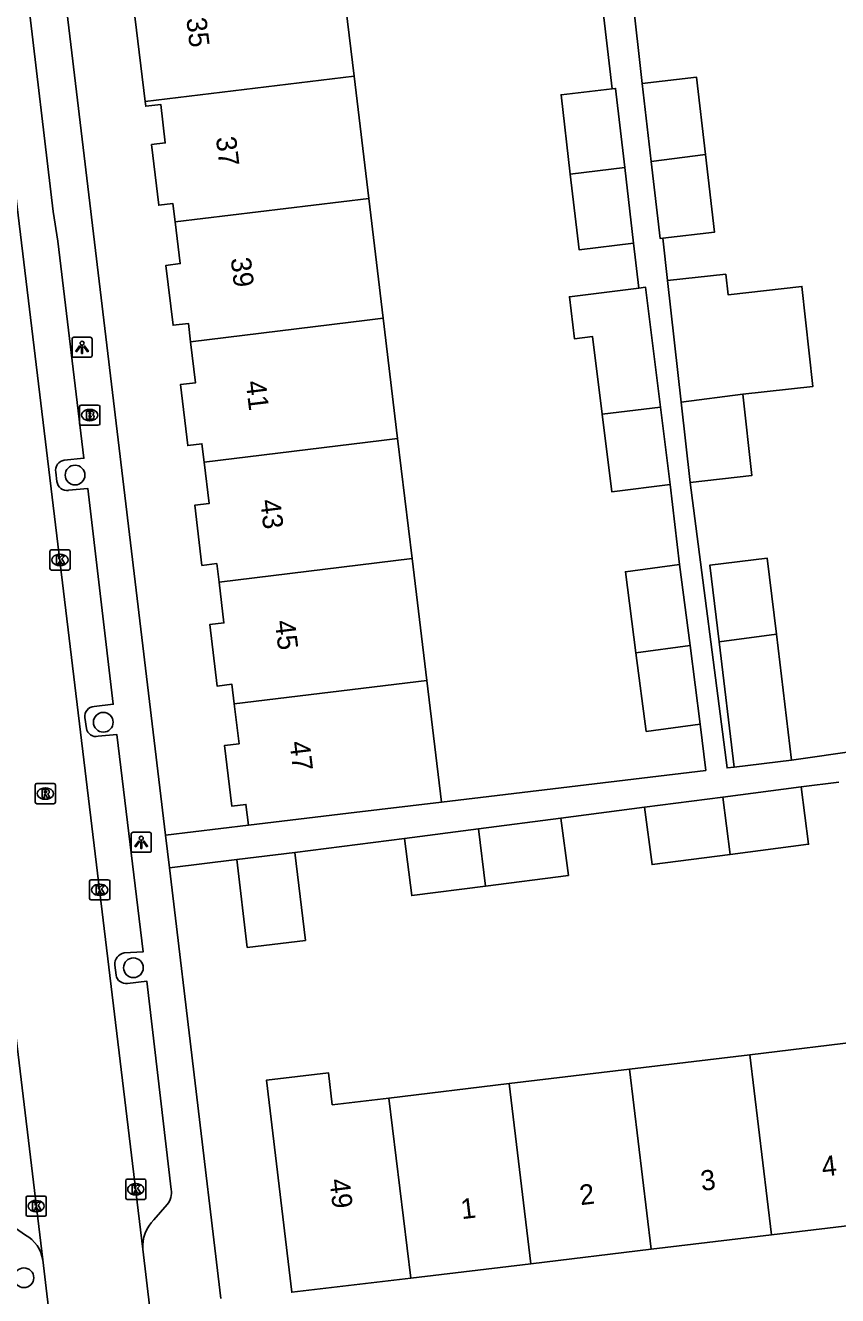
# Model space of a CAD drawing. Extents: x 162074 to 163034, y 381824 to 382557.
# Drawn here: x 162361.6 to 162401.9, y 382279.2 to 382342.2 of the extents above; entities that cross this region are included whole.
import ezdxf

# ---------------------------------------------------------------- set-up
doc = ezdxf.new("R2010")
doc.units = 0
for name, color, linetype in [('IMGEO_Boom', 7, 'Continuous'), ('IMGEO_Brandkraan', 7, 'Continuous'), ('IMGEO_Kolk', 7, 'Continuous'), ('IMGEO_Lichtpunt', 7, 'Continuous'), ('IMGEO_Pand', 7, 'Continuous'), ('IMGEO_Pand_nummerreeks', 7, 'Continuous'), ('IMGEO_Rijbaan_lokaal_open', 7, 'Continuous'), ('IMGEO_Rioolput', 7, 'Continuous'), ('IMGEO_Voetpad_open', 7, 'Continuous')]:
    doc.layers.add(name, color=color, linetype=linetype)

msp = doc.modelspace()

# ---------------------------------------------------------------- linework, layer by layer
at = {"layer": 'IMGEO_Boom'}
for centre in [(162364.081, 382319.909), (162365.485, 382307.641), (162366.981, 382295.456), (162361.545, 382280.073)]:
    msp.add_circle(centre, 0.489, dxfattribs=at)
at = {"layer": 'IMGEO_Brandkraan'}
for p, q in [((162364.309, 382322.46), (162364.309, 382323.312)), ((162364.384, 382323.386), (162365.236, 382323.386)), ((162364.797, 382323.166), (162364.822, 382323.166)), ((162365.31, 382323.312), (162365.31, 382322.46)), ((162365.236, 382322.386), (162364.384, 382322.386)), ((162364.82, 382322.606), (162364.795, 382322.606))]:
    msp.add_line(p, q, dxfattribs=at)
for points in [[(162364.309, 382322.46), (162364.309, 382323.312)], [(162364.384, 382323.386), (162365.236, 382323.386)], [(162364.657, 382323.086), (162364.657, 382322.686), (162364.87, 382322.686)], [(162364.888, 382323.086), (162364.657, 382323.086)], [(162364.836, 382323.005), (162364.782, 382323.005), (162364.782, 382322.929)], [(162364.782, 382322.929), (162364.835, 382322.929)], [(162364.844, 382322.853), (162364.782, 382322.853), (162364.782, 382322.772)], [(162365.31, 382323.312), (162365.31, 382322.46)], [(162365.236, 382322.386), (162364.384, 382322.386)], [(162364.782, 382322.772), (162364.844, 382322.772)]]:
    msp.add_lwpolyline(points, dxfattribs=at)
for centre, radius, start, end in [((162364.386, 382323.31), 0.0765, 91.55205, 178.44795), ((162364.386, 382323.31), 0.0765, 91.55205, 178.44795), ((162364.837, 382322.967), 0.0379, 267.82845, 90.93552), ((162364.845, 382322.812), 0.0404, 269.87594, 90.50774), ((162364.892, 382322.941), 0.145, 59.4692, 91.53667), ((162364.917, 382322.988), 0.0922, 285.51372, 58.15012), ((162364.922, 382322.796), 0.105, 301.31148, 78.98903), ((162365.234, 382323.31), 0.0765, 1.55205, 88.44795), ((162365.234, 382323.31), 0.0765, 1.55205, 88.44795), ((162364.386, 382322.462), 0.0765, 181.55205, 268.44795), ((162364.386, 382322.462), 0.0765, 181.55205, 268.44795), ((162364.876, 382322.937), 0.251, 268.66757, 293.53466), ((162365.234, 382322.462), 0.0765, 271.55205, 358.44795), ((162365.234, 382322.462), 0.0765, 271.55205, 358.44795)]:
    msp.add_arc(centre, radius, start, end, dxfattribs=at)
for centre, major_axis, ratio, start_param, end_param in [((162364.796, 382322.886), (-0.387, 0.002), 0.722429, 4.712389, 7.853982), ((162364.821, 382322.886), (-0.39, 0.002), 0.717154, 1.570796, 4.712389)]:
    msp.add_ellipse(centre, major_axis=major_axis, ratio=ratio, start_param=start_param, end_param=end_param, dxfattribs=at)
at = {"layer": 'IMGEO_Kolk'}
for p, q in [((162362.833, 382315.271), (162362.833, 382316.123)), ((162362.908, 382316.197), (162363.76, 382316.197)), ((162363.321, 382315.977), (162363.346, 382315.977)), ((162363.834, 382316.123), (162363.834, 382315.271)), ((162363.344, 382315.417), (162363.319, 382315.417)), ((162363.76, 382315.197), (162362.908, 382315.197)), ((162364.805, 382298.9), (162364.805, 382299.752)), ((162364.88, 382299.826), (162365.732, 382299.826)), ((162365.293, 382299.606), (162365.318, 382299.606)), ((162365.806, 382299.752), (162365.806, 382298.9)), ((162365.316, 382299.046), (162365.291, 382299.046)), ((162365.732, 382298.826), (162364.88, 382298.826)), ((162366.596, 382284.04), (162366.596, 382284.892)), ((162366.671, 382284.966), (162367.523, 382284.966)), ((162367.084, 382284.746), (162367.109, 382284.746)), ((162367.597, 382284.892), (162367.597, 382284.04)), ((162361.651, 382283.204), (162361.651, 382284.056)), ((162361.726, 382284.13), (162362.578, 382284.13)), ((162362.139, 382283.91), (162362.164, 382283.91)), ((162362.652, 382284.056), (162362.652, 382283.204)), ((162367.523, 382283.966), (162366.671, 382283.966)), ((162367.107, 382284.186), (162367.082, 382284.186)), ((162362.578, 382283.13), (162361.726, 382283.13)), ((162362.162, 382283.35), (162362.137, 382283.35))]:
    msp.add_line(p, q, dxfattribs=at)
for points in [[(162362.833, 382315.271), (162362.833, 382316.123)], [(162362.908, 382316.197), (162363.76, 382316.197)], [(162363.154, 382315.897), (162363.277, 382315.897), (162363.277, 382315.746), (162363.407, 382315.897), (162363.571, 382315.897), (162363.425, 382315.746), (162363.578, 382315.497), (162363.426, 382315.497), (162363.341, 382315.661), (162363.277, 382315.594), (162363.277, 382315.497), (162363.154, 382315.497), (162363.154, 382315.897)], [(162363.834, 382316.123), (162363.834, 382315.271)], [(162363.76, 382315.197), (162362.908, 382315.197)], [(162364.805, 382298.9), (162364.805, 382299.752)], [(162364.88, 382299.826), (162365.732, 382299.826)], [(162365.126, 382299.526), (162365.249, 382299.526), (162365.249, 382299.375), (162365.379, 382299.526), (162365.543, 382299.526), (162365.397, 382299.375), (162365.55, 382299.126), (162365.398, 382299.126), (162365.313, 382299.29), (162365.249, 382299.223), (162365.249, 382299.126), (162365.126, 382299.126), (162365.126, 382299.526)], [(162365.806, 382299.752), (162365.806, 382298.9)], [(162365.732, 382298.826), (162364.88, 382298.826)], [(162366.596, 382284.04), (162366.596, 382284.892)], [(162366.671, 382284.966), (162367.523, 382284.966)], [(162366.917, 382284.666), (162367.04, 382284.666), (162367.04, 382284.515), (162367.17, 382284.666), (162367.334, 382284.666), (162367.188, 382284.515), (162367.341, 382284.266), (162367.189, 382284.266), (162367.104, 382284.43), (162367.04, 382284.363), (162367.04, 382284.266), (162366.917, 382284.266), (162366.917, 382284.666)], [(162367.597, 382284.892), (162367.597, 382284.04)], [(162361.651, 382283.204), (162361.651, 382284.056)], [(162361.726, 382284.13), (162362.578, 382284.13)], [(162361.972, 382283.83), (162362.095, 382283.83), (162362.095, 382283.679), (162362.225, 382283.83), (162362.389, 382283.83), (162362.243, 382283.679), (162362.396, 382283.43), (162362.244, 382283.43), (162362.159, 382283.594), (162362.095, 382283.527), (162362.095, 382283.43), (162361.972, 382283.43), (162361.972, 382283.83)], [(162362.652, 382284.056), (162362.652, 382283.204)], [(162367.523, 382283.966), (162366.671, 382283.966)], [(162362.578, 382283.13), (162361.726, 382283.13)]]:
    msp.add_lwpolyline(points, dxfattribs=at)
for centre, start, end in [((162362.91, 382316.121), 91.55205, 178.44795), ((162362.91, 382316.121), 91.55205, 178.44795), ((162363.758, 382316.121), 1.55205, 88.44795), ((162363.758, 382316.121), 1.55205, 88.44795), ((162362.91, 382315.273), 181.55205, 268.44795), ((162362.91, 382315.273), 181.55205, 268.44795), ((162363.758, 382315.273), 271.55205, 358.44795), ((162363.758, 382315.273), 271.55205, 358.44795), ((162364.882, 382299.75), 91.55205, 178.44795), ((162364.882, 382299.75), 91.55205, 178.44795), ((162365.73, 382299.75), 1.55205, 88.44795), ((162365.73, 382299.75), 1.55205, 88.44795), ((162364.882, 382298.902), 181.55205, 268.44795), ((162364.882, 382298.902), 181.55205, 268.44795), ((162365.73, 382298.902), 271.55205, 358.44795), ((162365.73, 382298.902), 271.55205, 358.44795), ((162366.673, 382284.89), 91.55205, 178.44795), ((162366.673, 382284.89), 91.55205, 178.44795), ((162367.521, 382284.89), 1.55205, 88.44795), ((162367.521, 382284.89), 1.55205, 88.44795), ((162361.728, 382284.054), 91.55205, 178.44795), ((162361.728, 382284.054), 91.55205, 178.44795), ((162362.576, 382284.054), 1.55205, 88.44795), ((162362.576, 382284.054), 1.55205, 88.44795), ((162366.673, 382284.042), 181.55205, 268.44795), ((162366.673, 382284.042), 181.55205, 268.44795), ((162367.521, 382284.042), 271.55205, 358.44795), ((162367.521, 382284.042), 271.55205, 358.44795), ((162361.728, 382283.206), 181.55205, 268.44795), ((162361.728, 382283.206), 181.55205, 268.44795), ((162362.576, 382283.206), 271.55205, 358.44795), ((162362.576, 382283.206), 271.55205, 358.44795)]:
    msp.add_arc(centre, 0.0765, start, end, dxfattribs=at)
for centre, major_axis, ratio, start_param, end_param in [((162363.32, 382315.697), (-0.387, 0.002), 0.722429, 4.712389, 7.853982), ((162363.345, 382315.697), (-0.39, 0.002), 0.717154, 1.570796, 4.712389), ((162365.292, 382299.326), (-0.387, 0.002), 0.722429, 4.712389, 7.853982), ((162365.317, 382299.326), (-0.39, 0.002), 0.717154, 1.570796, 4.712389), ((162367.083, 382284.466), (-0.387, 0.002), 0.722429, 4.712389, 7.853982), ((162367.108, 382284.466), (-0.39, 0.002), 0.717154, 1.570796, 4.712389), ((162362.138, 382283.63), (-0.387, 0.002), 0.722429, 4.712389, 7.853982), ((162362.163, 382283.63), (-0.39, 0.002), 0.717154, 1.570796, 4.712389)]:
    msp.add_ellipse(centre, major_axis=major_axis, ratio=ratio, start_param=start_param, end_param=end_param, dxfattribs=at)
at = {"layer": 'IMGEO_Lichtpunt'}
for p, q in [((162363.933, 382326.656), (162363.933, 382325.849)), ((162363.933, 382326.656), (162363.933, 382325.849)), ((162364.835, 382326.751), (162364.027, 382326.751)), ((162364.835, 382326.751), (162364.027, 382326.751)), ((162364.929, 382325.849), (162364.929, 382326.656)), ((162364.929, 382325.849), (162364.929, 382326.656)), ((162364.027, 382325.755), (162364.835, 382325.755)), ((162364.027, 382325.755), (162364.835, 382325.755)), ((162366.869, 382302.089), (162366.869, 382301.282)), ((162366.869, 382302.089), (162366.869, 382301.282)), ((162367.771, 382302.184), (162366.963, 382302.184)), ((162367.771, 382302.184), (162366.963, 382302.184)), ((162367.865, 382301.282), (162367.865, 382302.089)), ((162367.865, 382301.282), (162367.865, 382302.089)), ((162366.963, 382301.188), (162367.771, 382301.188)), ((162366.963, 382301.188), (162367.771, 382301.188))]:
    msp.add_line(p, q, dxfattribs=at)
for points in [[(162364.307, 382326.32), (162364.346, 382326.292), (162364.158, 382326.03), (162364.12, 382326.057), (162364.307, 382326.32)], [(162364.409, 382326.272), (162364.456, 382326.272), (162364.456, 382325.95), (162364.409, 382325.95), (162364.409, 382326.272)], [(162364.519, 382326.292), (162364.557, 382326.319), (162364.744, 382326.057), (162364.705, 382326.029), (162364.519, 382326.292)], [(162367.243, 382301.753), (162367.282, 382301.725), (162367.094, 382301.463), (162367.056, 382301.49), (162367.243, 382301.753)], [(162367.345, 382301.705), (162367.392, 382301.705), (162367.392, 382301.383), (162367.345, 382301.383), (162367.345, 382301.705)], [(162367.455, 382301.725), (162367.493, 382301.752), (162367.68, 382301.49), (162367.641, 382301.462), (162367.455, 382301.725)]]:
    msp.add_lwpolyline(points, dxfattribs=at)
for centre in [(162364.432, 382326.454), (162367.368, 382301.887)]:
    msp.add_circle(centre, 0.0994, dxfattribs=at)
for centre, start, end in [((162364.027, 382326.656), 90, 180), ((162364.027, 382326.656), 90, 180), ((162364.835, 382326.656), 0, 90), ((162364.835, 382326.656), 0, 90), ((162364.027, 382325.849), 180, 270), ((162364.027, 382325.849), 180, 270), ((162364.835, 382325.849), 270, 0), ((162364.835, 382325.849), 270, 360), ((162366.963, 382302.089), 90, 180), ((162366.963, 382302.089), 90, 180), ((162367.771, 382302.089), 0, 90), ((162367.771, 382302.089), 0, 90), ((162366.963, 382301.282), 180, 270), ((162366.963, 382301.282), 180, 270), ((162367.771, 382301.282), 270, 0), ((162367.771, 382301.282), 270, 360)]:
    msp.add_arc(centre, 0.0946, start, end, dxfattribs=at)
at = {"layer": 'IMGEO_Pand'}
for points in [[(162377.93, 382339.707), (162377.209, 382345.696)], [(162366.837, 382344.447), (162367.56, 382338.443)], [(162367.56, 382338.443), (162377.93, 382339.707)], [(162378.661, 382333.63), (162377.93, 382339.707)], [(162392.229, 382339.34), (162394.934, 382339.654), (162395.38, 382335.82)], [(162392.679, 382335.466), (162392.229, 382339.34)], [(162390.74, 382339.078), (162388.208, 382338.784), (162388.667, 382334.839)], [(162391.37, 382335.166), (162390.913, 382339.098), (162390.74, 382339.078)], [(162367.56, 382338.443), (162367.588, 382338.21), (162368.333, 382338.3), (162368.563, 382336.391), (162367.877, 382336.308), (162368.24, 382333.3), (162368.941, 382333.384), (162369.051, 382332.469)], [(162395.38, 382335.82), (162392.679, 382335.466)], [(162392.679, 382335.466), (162393.122, 382331.651), (162393.266, 382331.668)], [(162393.266, 382331.668), (162395.828, 382331.966), (162395.38, 382335.82)], [(162388.667, 382334.839), (162391.37, 382335.166)], [(162388.667, 382334.839), (162389.102, 382331.095), (162391.807, 382331.41)], [(162391.807, 382331.41), (162391.37, 382335.166)], [(162369.051, 382332.469), (162378.661, 382333.63)], [(162379.376, 382327.691), (162378.661, 382333.63)], [(162369.051, 382332.469), (162369.3, 382330.402), (162368.591, 382330.317), (162368.949, 382327.345), (162369.711, 382327.436), (162369.82, 382326.528)], [(162393.5, 382329.559), (162396.383, 382329.879), (162396.496, 382328.861), (162400.162, 382329.268), (162400.712, 382324.311), (162397.226, 382323.924)], [(162392.065, 382329.19), (162388.62, 382328.759), (162388.882, 382326.667), (162389.773, 382326.778), (162390.254, 382322.937)], [(162393.149, 382323.28), (162392.405, 382329.232), (162392.065, 382329.19)], [(162394.169, 382323.524), (162393.5, 382329.559)], [(162369.82, 382326.528), (162378.575, 382327.596), (162379.376, 382327.691)], [(162380.094, 382321.725), (162379.376, 382327.691)], [(162369.82, 382326.528), (162370.066, 382324.487), (162369.315, 382324.397), (162369.678, 382321.376), (162370.383, 382321.461), (162370.492, 382320.556)], [(162397.226, 382323.924), (162394.169, 382323.524)], [(162394.169, 382323.524), (162394.611, 382319.544)], [(162397.226, 382323.924), (162397.674, 382319.883), (162394.611, 382319.544)], [(162390.254, 382322.937), (162393.149, 382323.28)], [(162390.254, 382322.937), (162390.736, 382319.076), (162393.629, 382319.438)], [(162393.629, 382319.438), (162393.149, 382323.28)], [(162380.094, 382321.725), (162379.302, 382321.631), (162370.492, 382320.556)], [(162380.812, 382315.761), (162380.094, 382321.725)], [(162370.492, 382320.556), (162370.74, 382318.499), (162370.023, 382318.413), (162370.382, 382315.425), (162371.117, 382315.513), (162371.228, 382314.591)], [(162371.228, 382314.591), (162380.812, 382315.761)], [(162381.539, 382309.721), (162380.812, 382315.761)], [(162394.084, 382315.463), (162391.4, 382315.112), (162391.926, 382311.092)], [(162394.61, 382311.445), (162394.084, 382315.463)], [(162396.053, 382311.634), (162395.598, 382315.442), (162398.445, 382315.782), (162398.895, 382312.007)], [(162371.228, 382314.591), (162371.471, 382312.576), (162370.767, 382312.491), (162371.134, 382309.439), (162371.87, 382309.528), (162371.987, 382308.558)], [(162396.053, 382311.634), (162398.895, 382312.007)], [(162396.794, 382305.418), (162396.053, 382311.634)], [(162398.895, 382312.007), (162399.641, 382305.758)], [(162391.926, 382311.092), (162394.61, 382311.445)], [(162391.926, 382311.092), (162392.437, 382307.188), (162395.121, 382307.54)], [(162395.121, 382307.54), (162394.61, 382311.445)], [(162381.539, 382309.721), (162371.987, 382308.558)], [(162382.266, 382303.683), (162381.539, 382309.721)], [(162371.987, 382308.558), (162372.226, 382306.572), (162371.498, 382306.484), (162371.86, 382303.478), (162372.568, 382303.563), (162372.693, 382302.53)], [(162396.794, 382305.418), (162399.641, 382305.758)], [(162396.243, 382303.927), (162392.355, 382303.424)], [(162400.13, 382304.43), (162396.243, 382303.927)], [(162396.611, 382301.085), (162396.243, 382303.927)], [(162396.611, 382301.085), (162400.498, 382301.588), (162400.13, 382304.43)], [(162372.693, 382302.53), (162377.658, 382303.128), (162382.266, 382303.683)], [(162392.355, 382303.424), (162392.723, 382300.582), (162396.611, 382301.085)], [(162388.204, 382302.886), (162384.107, 382302.356)], [(162384.451, 382299.511), (162388.572, 382300.044), (162388.204, 382302.886)], [(162384.107, 382302.356), (162380.429, 382301.88)], [(162384.451, 382299.511), (162384.107, 382302.356)], [(162380.429, 382301.88), (162380.797, 382299.038), (162384.451, 382299.511)], [(162374.991, 382301.173), (162372.108, 382300.826)], [(162372.108, 382300.826), (162372.632, 382296.471), (162375.516, 382296.818), (162374.991, 382301.173)], [(162403.546, 382291.857), (162397.575, 382291.142)], [(162397.575, 382291.142), (162391.605, 382290.427)], [(162397.575, 382291.142), (162398.655, 382282.201)], [(162379.663, 382288.995), (162376.847, 382288.658), (162376.657, 382290.246), (162373.578, 382289.877), (162374.837, 382279.352), (162380.743, 382280.059)], [(162391.605, 382290.427), (162385.635, 382289.711)], [(162392.684, 382281.487), (162391.605, 382290.427)], [(162385.635, 382289.711), (162379.663, 382288.995)], [(162386.714, 382280.773), (162385.635, 382289.711)], [(162380.743, 382280.059), (162379.663, 382288.995)], [(162398.655, 382282.201), (162404.626, 382282.915)], [(162392.684, 382281.487), (162398.655, 382282.201)], [(162386.714, 382280.773), (162392.684, 382281.487)], [(162380.743, 382280.059), (162386.714, 382280.773)]]:
    msp.add_lwpolyline(points, dxfattribs=at)
at = {"layer": 'IMGEO_Rijbaan_lokaal_open'}
for points in [[(162354.936, 382343.632), (162362.475, 382280.956)], [(162367.454, 382281.495), (162361.255, 382332.813), (162359.881, 382344.208)], [(162367.454, 382281.495), (162367.807, 382278.409)], [(162362.933, 382277.183), (162362.475, 382280.956)]]:
    msp.add_lwpolyline(points, dxfattribs=at)
at = {"layer": 'IMGEO_Rioolput'}
for p, q in [((162362.106, 382303.676), (162362.106, 382304.528)), ((162362.181, 382304.602), (162363.033, 382304.602)), ((162363.107, 382304.528), (162363.107, 382303.676)), ((162362.594, 382304.382), (162362.619, 382304.382)), ((162363.033, 382303.602), (162362.181, 382303.602)), ((162362.617, 382303.822), (162362.592, 382303.822))]:
    msp.add_line(p, q, dxfattribs=at)
for points in [[(162362.106, 382303.676), (162362.106, 382304.528)], [(162362.181, 382304.602), (162363.033, 382304.602)], [(162363.107, 382304.528), (162363.107, 382303.676)], [(162362.695, 382304.3), (162362.443, 382304.302), (162362.443, 382303.902)], [(162362.443, 382303.902), (162362.567, 382303.902), (162362.567, 382304.064), (162362.578, 382304.064)], [(162362.621, 382304.221), (162362.567, 382304.221), (162362.567, 382304.14)], [(162362.567, 382304.14), (162362.619, 382304.14)], [(162362.625, 382304.035), (162362.696, 382303.902), (162362.836, 382303.902), (162362.771, 382304.028)], [(162363.033, 382303.602), (162362.181, 382303.602)]]:
    msp.add_lwpolyline(points, dxfattribs=at)
for centre, radius, start, end in [((162362.183, 382304.526), 0.0765, 91.55205, 178.44795), ((162362.183, 382304.526), 0.0765, 91.55205, 178.44795), ((162363.031, 382304.526), 0.0765, 1.55205, 88.44795), ((162363.031, 382304.526), 0.0765, 1.55205, 88.44795), ((162362.577, 382304.011), 0.0533, 26.02933, 88.69889), ((162362.603, 382304.329), 0.19, 274.7715, 282.96867), ((162362.627, 382304.125), 0.0964, 77.00612, 93.18647), ((162362.641, 382304.182), 0.0378, 276.66336, 79.67722), ((162362.694, 382304.19), 0.109, 350.36119, 89.41601), ((162362.692, 382304.19), 0.112, 277.58423, 350.98172), ((162362.676, 382303.975), 0.108, 29.51342, 73.79051), ((162362.183, 382303.678), 0.0765, 181.55205, 268.44795), ((162362.183, 382303.678), 0.0765, 181.55205, 268.44795), ((162363.031, 382303.678), 0.0765, 271.55205, 358.44795), ((162363.031, 382303.678), 0.0765, 271.55205, 358.44795)]:
    msp.add_arc(centre, radius, start, end, dxfattribs=at)
for centre, major_axis, ratio, start_param, end_param in [((162362.593, 382304.102), (-0.387, 0.002), 0.722429, 4.712389, 7.853982), ((162362.618, 382304.102), (-0.39, 0.002), 0.717154, 1.570796, 4.712389)]:
    msp.add_ellipse(centre, major_axis=major_axis, ratio=ratio, start_param=start_param, end_param=end_param, dxfattribs=at)
at = {"layer": 'IMGEO_Voetpad_open'}
for points in [[(162360.752, 382343.659), (162361.723, 382343.762), (162362.997, 382332.995), (162363.227, 382331.519), (162364.525, 382320.745), (162363.547, 382320.643)], [(162368.571, 382302.036), (162363.534, 382344.049)], [(162390.212, 382343.624), (162390.74, 382339.078)], [(162391.732, 382343.805), (162392.229, 382339.34)], [(162393.266, 382331.668), (162393.5, 382329.559)], [(162391.807, 382331.41), (162392.065, 382329.19)], [(162363.124, 382320.055), (162363.179, 382319.584)], [(162363.754, 382319.152), (162364.714, 382319.249), (162365.982, 382308.535), (162365.031, 382308.418)], [(162393.629, 382319.438), (162394.084, 382315.463)], [(162394.611, 382319.544), (162396.447, 382305.373), (162396.794, 382305.418)], [(162364.574, 382307.872), (162364.645, 382307.34)], [(162365.233, 382306.951), (162366.156, 382307.042), (162367.468, 382296.256), (162366.52, 382296.203)], [(162395.121, 382307.54), (162395.394, 382305.251), (162382.266, 382303.683)], [(162399.641, 382305.758), (162409.908, 382307.23)], [(162400.13, 382304.43), (162401.998, 382304.672)], [(162388.204, 382302.886), (162392.355, 382303.424)], [(162372.693, 382302.53), (162368.571, 382302.036)], [(162368.764, 382300.425), (162368.571, 382302.036)], [(162374.991, 382301.173), (162380.429, 382301.88)], [(162368.764, 382300.425), (162372.108, 382300.826)], [(162371.326, 382279.053), (162368.764, 382300.425)], [(162366.049, 382295.594), (162366.115, 382295.091)], [(162366.684, 382294.682), (162367.639, 382294.796), (162368.858, 382284.454)], [(162368.655, 382283.709), (162367.993, 382282.95)], [(162361.617, 382282.194), (162360.801, 382282.759)]]:
    msp.add_lwpolyline(points, dxfattribs=at)
for centre, radius, start, end in [((162363.601, 382320.158), 0.488, 96.37999, 192.15845), ((162363.688, 382319.663), 0.516, 188.86003, 277.30457), ((162365.043, 382307.944), 0.474, 91.4519, 188.68969), ((162365.115, 382307.412), 0.476, 188.69213, 284.33345), ((162366.654, 382295.613), 0.605, 102.75408, 181.80925), ((162366.608, 382295.176), 0.5, 189.79334, 278.78913), ((162367.976, 382284.294), 0.896, 319.23482, 10.28098), ((162369.261, 382281.653), 1.813, 134.34368, 185.00235), ((162360.827, 382280.73), 1.663, 7.7955, 61.65255)]:
    msp.add_arc(centre, radius, start, end, dxfattribs=at)

# ---------------------------------------------------------------- texts
at = {"layer": 'IMGEO_Pand_nummerreeks'}
for s, rotation, p in [('35', 276.86596, (162369.602, 382342.567)), ('37', 276.94898, (162371.072, 382336.658)), ('39', 276.94898, (162371.804, 382330.658)), ('41', 276.94898, (162372.549, 382324.545)), ('43', 276.94898, (162373.266, 382318.656)), ('45', 276.94898, (162373.998, 382312.656)), ('47', 276.94898, (162374.729, 382306.655)), ('4', 6.70509, (162401.201, 382285.087)), ('3', 6.70509, (162395.191, 382284.381)), ('49', 276.82131, (162376.707, 382284.94)), ('2', 6.70509, (162389.179, 382283.674)), ('1', 6.70509, (162383.283, 382282.98))]:
    msp.add_text(s, height=1, rotation=rotation, dxfattribs=at).set_placement(p)

doc.saveas('drawing.dxf')
